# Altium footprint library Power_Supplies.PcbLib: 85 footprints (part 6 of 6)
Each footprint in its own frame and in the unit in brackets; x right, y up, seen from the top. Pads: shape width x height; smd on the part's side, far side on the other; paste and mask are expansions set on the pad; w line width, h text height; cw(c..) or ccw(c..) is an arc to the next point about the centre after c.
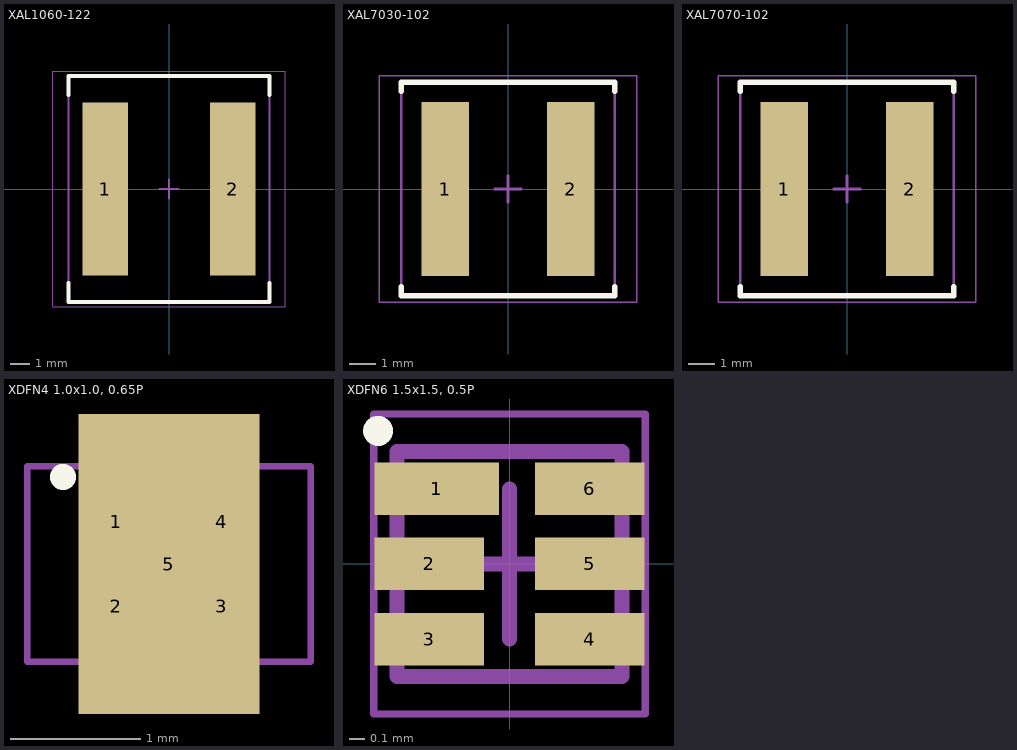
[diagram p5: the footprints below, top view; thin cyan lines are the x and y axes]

## XAL1060-122 [mm] "XAL1060, Coilcraft"
height 6
pads (2):
  rect 2.38x9 smd: 1(-3.325,0) 2(3.325,0)
Top Overlay:
  lines w0.2: -5.25,-4.9 -5.25,-5.9 5.25,-5.9 5.25,-4.9 ; -5.25,4.9 -5.25,5.9 5.25,5.9 5.25,4.9
Mechanical 13:
  lines w0.1: -5.25,-5.9 -5.25,5.9 5.25,5.9 5.25,-5.9 -5.25,-5.9
Mechanical 15:
  lines w0.05: -6.075,-6.15 -6.075,6.15 6.075,6.15 6.075,-6.15 -6.075,-6.15
  lines w0.1: -0.5,0 0.5,0 ; 0,-0.5 0,0.5
3D body "Coilcraft-XAL1060.STEP": height 5.9, standoff -0.1, extent -5.25,-5.9 5.25,5.9

## XAL7030-102 [mm] "Precision Wire Wound Inductor, 2-Leads, Body 7.50x7.50mm, IPC Medium Density"
height 3.1
pads (2):
  rect 1.78x6.52 smd: 1(-2.36,0) 2(2.36,0)
Top Overlay:
  lines w0.2: -4,-3.66 -4,-4 4,-4 4,-3.66 ; -4,3.66 -4,4 4,4 4,3.66
Mechanical 13:
  lines w0.1: -4,-4 4,-4 4,4 -4,4 -4,-4
Mechanical 15:
  lines w0.05: -4.825,-4.25 4.825,-4.25 4.825,4.25 -4.825,4.25 -4.825,-4.25
  lines w0.1: -0.5,0 0.5,0 ; 0,-0.5 0,0.5
3D body "Coilcraft-XAL7030-102.STEP": height 3, standoff -0.1, extent -4,-4 4,4

## XAL7070-102 [mm] "Precision Wire Wound Inductor, 2-Leads, Body 7.50x7.50mm, IPC Medium Density"
height 7
pads (2):
  rect 1.78x6.52 smd: 1(-2.36,0) 2(2.36,0)
Top Overlay:
  lines w0.2: -4,-3.66 -4,-4 4,-4 4,-3.66 ; -4,3.66 -4,4 4,4 4,3.66
Mechanical 13:
  lines w0.1: -4,-4 4,-4 4,4 -4,4 -4,-4
Mechanical 15:
  lines w0.05: -4.825,-4.25 4.825,-4.25 4.825,4.25 -4.825,4.25 -4.825,-4.25
  lines w0.1: -0.5,0 0.5,0 ; 0,-0.5 0,0.5
3D body "Coilcraft-XAL7070.STEP": height 6.6, standoff -0.4, extent -3.85,-4 3.85,4

## XDFN4 1.0x1.0, 0.65P [mm] "XDFN4 1.0x1.0, 0.65P, CASE 711AJ, Issue A"
height 0.43
pads (5):
  rect 0.39x0.26 smd: 1(19.107,38.097) 2(19.107,37.447) 3(19.917,37.447) 4(19.917,38.097)
  rect 1.39x2.3 smd: 5(19.512,37.772)
Top Overlay:
  circle w0.1: c18.699,38.439 r0.05
Mechanical 13:
  lines w0.1: 19.012,37.272 19.012,38.272 20.012,38.272 20.012,37.272 19.012,37.272
Mechanical 15:
  lines w0.05: 18.427,37.022 18.427,38.522 20.597,38.522 20.597,37.022 18.427,37.022
  lines w0.1: 19.012,37.772 20.012,37.772 ; 19.512,37.272 19.512,38.272
3D body "XDFN4 1.0x1.0, 0.65P.step": height 0.43, standoff 0, extent -207256.111,-207237.85 -207255.109,-207236.85

## XDFN6 1.5x1.5, 0.5P [mm]
height 0.45
pads (6):
  rect 0.83x0.35 smd: 1(-0.485,0.5)
  rect 0.73x0.35 smd: 2(-0.535,0) 3(-0.535,-0.5) 4(0.535,-0.5) 5(0.535,0) 6(0.535,0.5)
Top Overlay:
  circle w0.1: c-0.877,0.887 r0.05
Mechanical 13:
  lines w0.1: -0.75,-0.75 -0.75,0.75 0.75,0.75 0.75,-0.75 -0.75,-0.75
Mechanical 15:
  lines w0.05: -0.905,-1 -0.905,1 0.905,1 0.905,-1 -0.905,-1
  lines w0.1: -0.5,0 0.5,0 ; 0,-0.5 0,0.5
3D body: height 0.45, standoff 0.05, extent -0.75,-0.75 0.75,0.75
